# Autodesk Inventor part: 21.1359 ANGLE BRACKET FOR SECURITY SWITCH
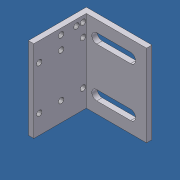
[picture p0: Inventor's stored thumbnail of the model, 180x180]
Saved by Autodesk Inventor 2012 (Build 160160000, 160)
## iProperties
Created: 2007-05
Part Number: 21.1359 ANGLE BRACKET FOR SECURITY SWITCH
Document SubType Name: Modeling
Designer: Andy Moles
Material: Aluminum-6061
Mass: 98.0756 g
Surface Area: 179.157 cm^2
Volume: 36.1903 cm^3
Density: 2.71 g/cm^3
Author: Andy Moles
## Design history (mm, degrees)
sketch "Sketch1"
  geometry: L1 (0, 0)-(0, -53); L2 (0, 0)-(60, 0); L3 (60, 0)-(60, -5); L4 (60, -5)-(5, -5); L5 (5, -5)-(5, -53); L6 (5, -53)-(0, -53)
  constraints: 12 end point, 3 perpendicular, 2 parallel, 1 vertical
  dimensions: "d0" = 60 distance of L1.start L2.end; "d1" = 53 distance of L1.start L1.end; "d2" = 5 distance between parallel lines of L4 L2; "d3" = 5 distance of L5.end L1.end
extrude "Extrusion1" new body sketch "Sketch1" stored distance "d4" = 75; taper "d5" = 0 deg
sketch "Sketch2"
  geometry: L1 (60, 75)-(0, 75) reference; L2 (0, 0)-(0, 75) reference; L3 (14.5, 64.5)-(45.5, 64.5); L4 (14.5, 55.5)-(45.5, 55.5); L5 (60, 75)-(60, 0) reference; L6 (0, 37.5)-(-19.158, 37.5); L7 (14.5, 10.5)-(45.5, 10.5); L8 (14.5, 19.5)-(45.5, 19.5); A1 r 4.5 centre (14.5, 60) between (14.5, 64.5) and (14.5, 55.5); A2 r 4.5 centre (45.5, 60) between (45.5, 55.5) and (45.5, 64.5); A3 r 4.5 centre (14.5, 15) between (14.5, 19.5) and (14.5, 10.5); A4 r 4.5 centre (45.5, 15) between (45.5, 10.5) and (45.5, 19.5)
  constraints: 10 end point, 8 point on circle, 6 symmetric about line, 4 centre point, 2 perpendicular, 2 tangent, 1 horizontal alignment, 1 parallel, 2 other
  dimensions: "d6" = 9 diameter of A2; "d7" = 9 diameter of A1; "d8" = 14.5 distance from line of A1.centre L2; "d9" = 15 distance from line of A1.centre L1; "d10" = 45.5 distance from line of A2.centre L2
extrude "Extrusion2" cut sketch "Sketch2" distance "d11" = 75; taper "d12" = 0 deg
sketch "Sketch3"
  geometry: L1 (-75, 53)-(-75, 0) reference; L2 (-75, 0)-(0, 0) reference; 10 further points
  constraints: 6 vertical alignment, 5 horizontal alignment
  dimensions: "d13" = 40 distance of point (-17.5, 5) point (-57.5, 5); "d14" = 75 distance of L1.end L2.end (derived); "d15" = 17.5 distance from line of point (-57.5, 5) L1 (= -0.5 x d13 + 0.5 x d14); "d16" = 5 distance from line of point (-57.5, 5) L2; "d17" = 25 distance from line of point (-57.5, 25) L2; "d18" = 45 distance from line of point (-57.5, 45) L2; "d38" = 52 horizontal distance of point (-5.5, 25) point (-57.5, 5); "d39" = 14 distance of point (-5.5, 39) point (-5.5, 25)
hole "Hole1" sketch "Sketch3" at (-57.5, 5), (-57.5, 25), (-57.5, 45), (-17.5, 45), (-17.5, 25), (-17.5, 5), (-5.5, 45), (-5.5, 39), (-5.5, 25) diameter "d19" = 5; stored, may be unused: countersink angle "d23" = 90 deg, drill point angle "d25" = 118 deg; dims "d20" = 6, "d21" = 4, "d22" = 2, "d24" = 8
thread "Thread1" dims "d26" = 10, "d27" = 0
thread "Thread2" dims "d28" = 10, "d29" = 0
thread "Thread3" dims "d30" = 10, "d31" = 0
thread "Thread4" dims "d32" = 10, "d33" = 0
thread "Thread5" dims "d34" = 10, "d35" = 0
thread "Thread6" dims "d36" = 10, "d37" = 0
thread "Thread7" dims "d40" = 10, "d41" = 0
thread "Thread8" dims "d42" = 10, "d43" = 0
thread "Thread9" dims "d44" = 10, "d45" = 0
body "Solid1"
